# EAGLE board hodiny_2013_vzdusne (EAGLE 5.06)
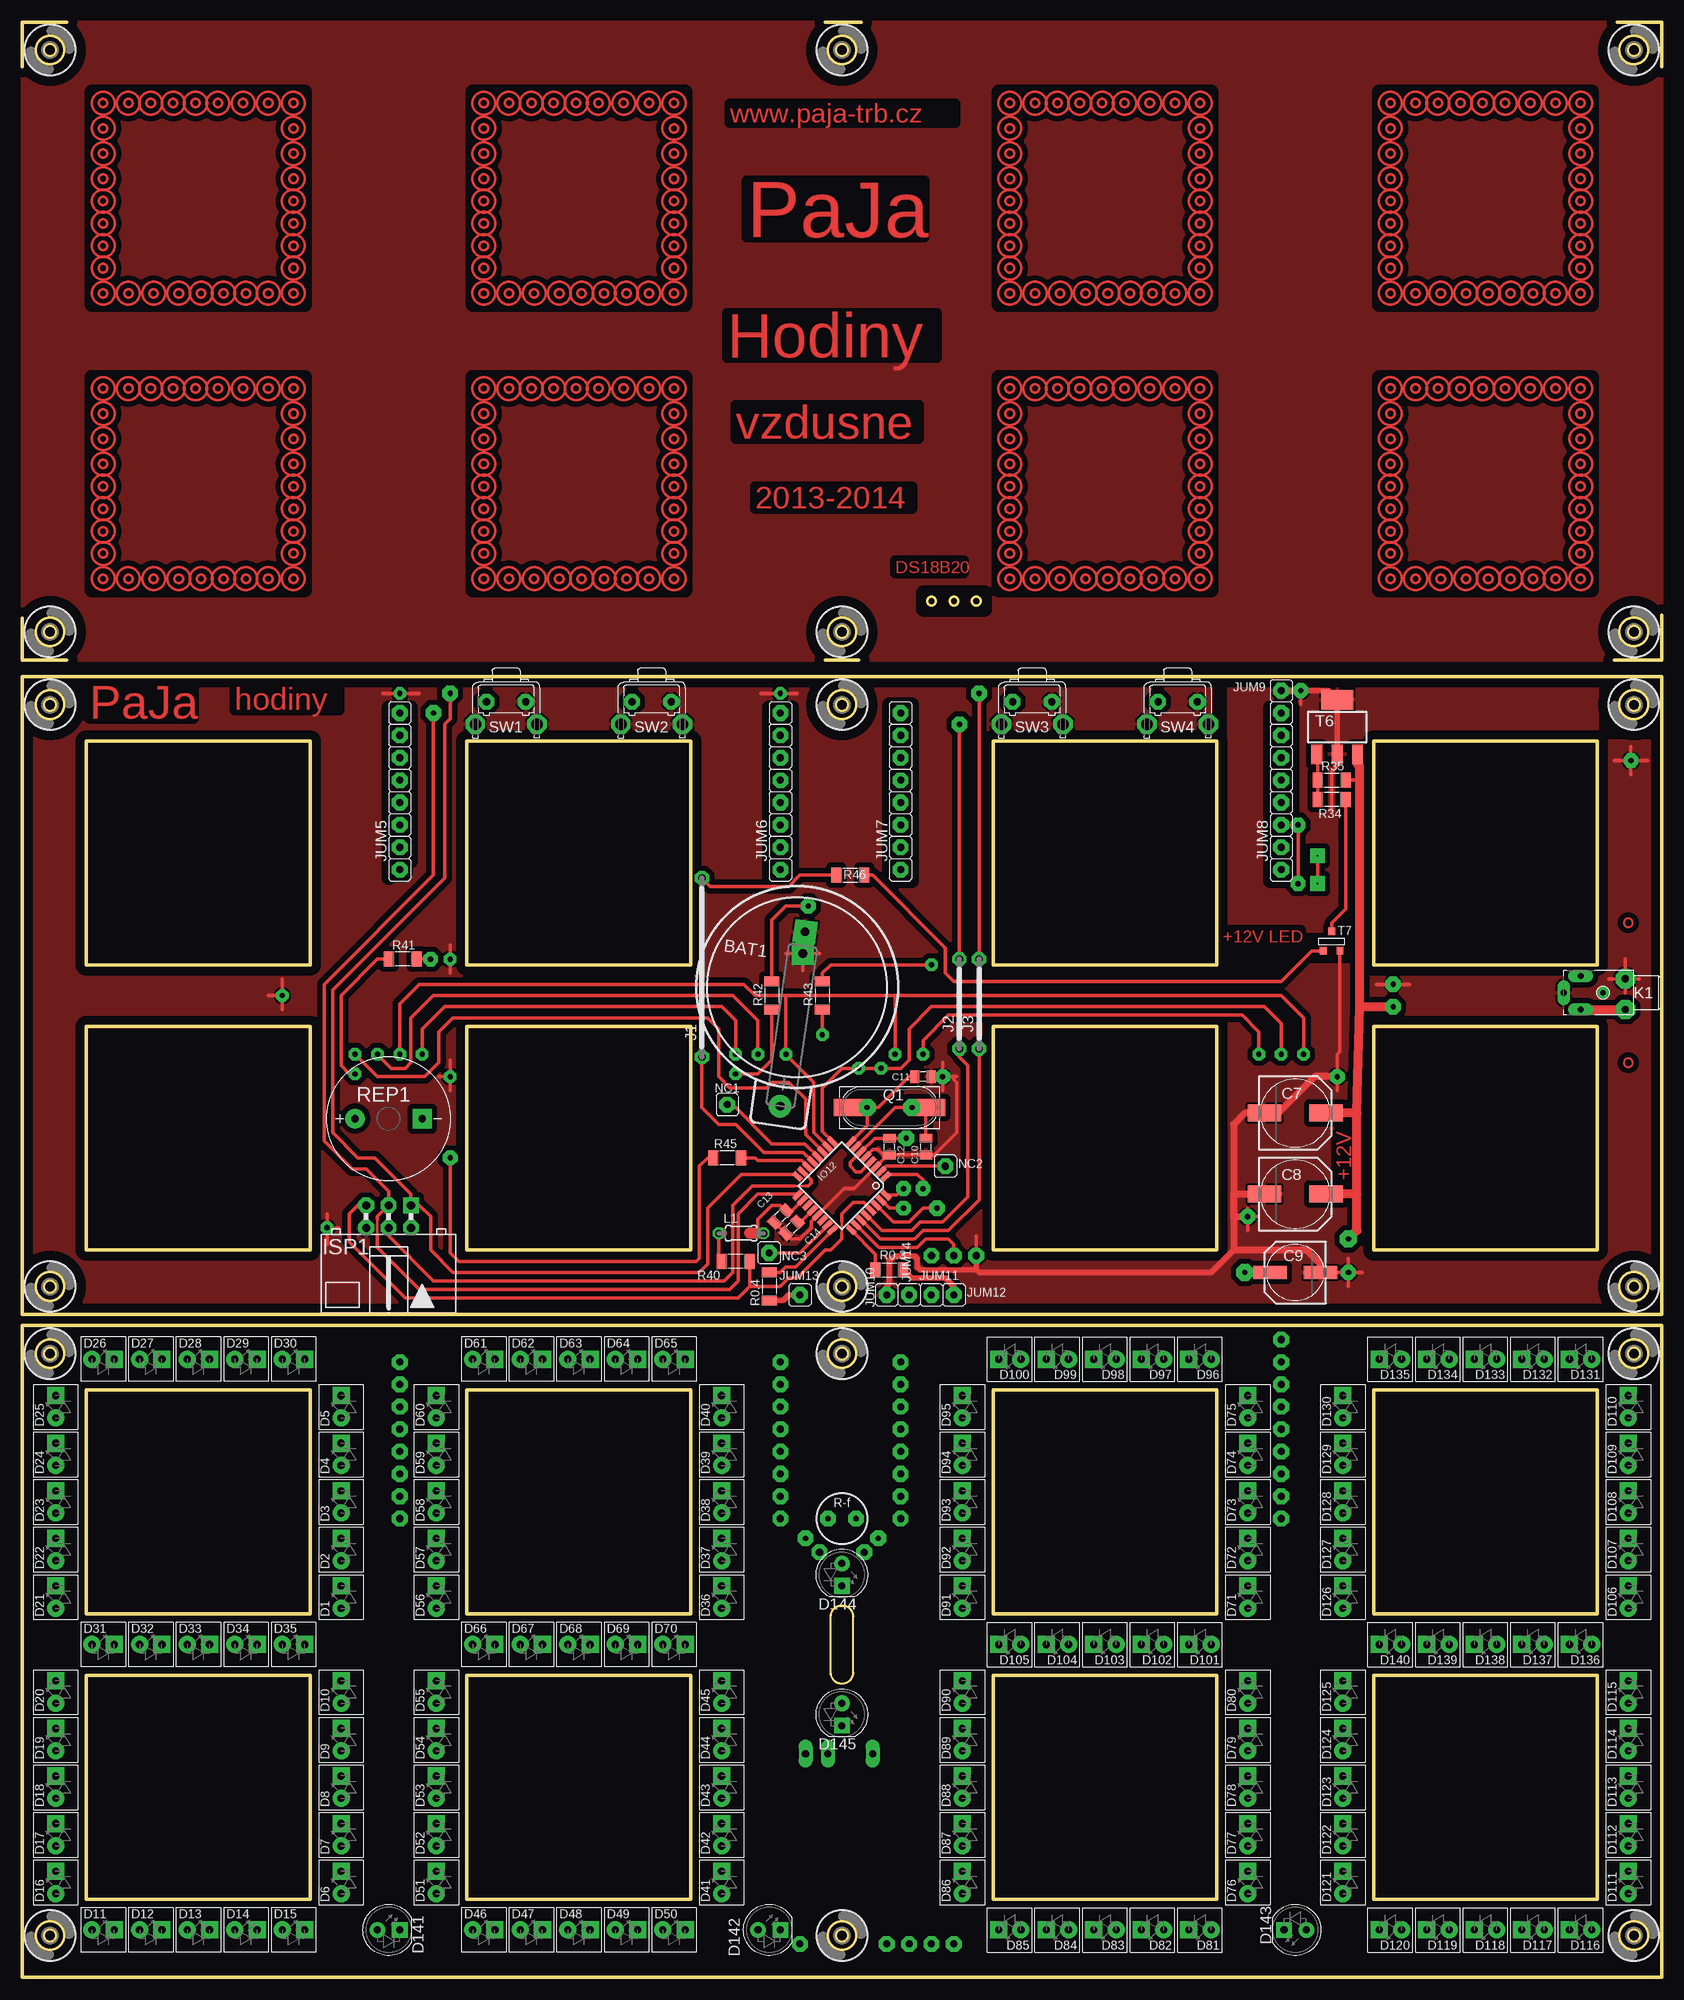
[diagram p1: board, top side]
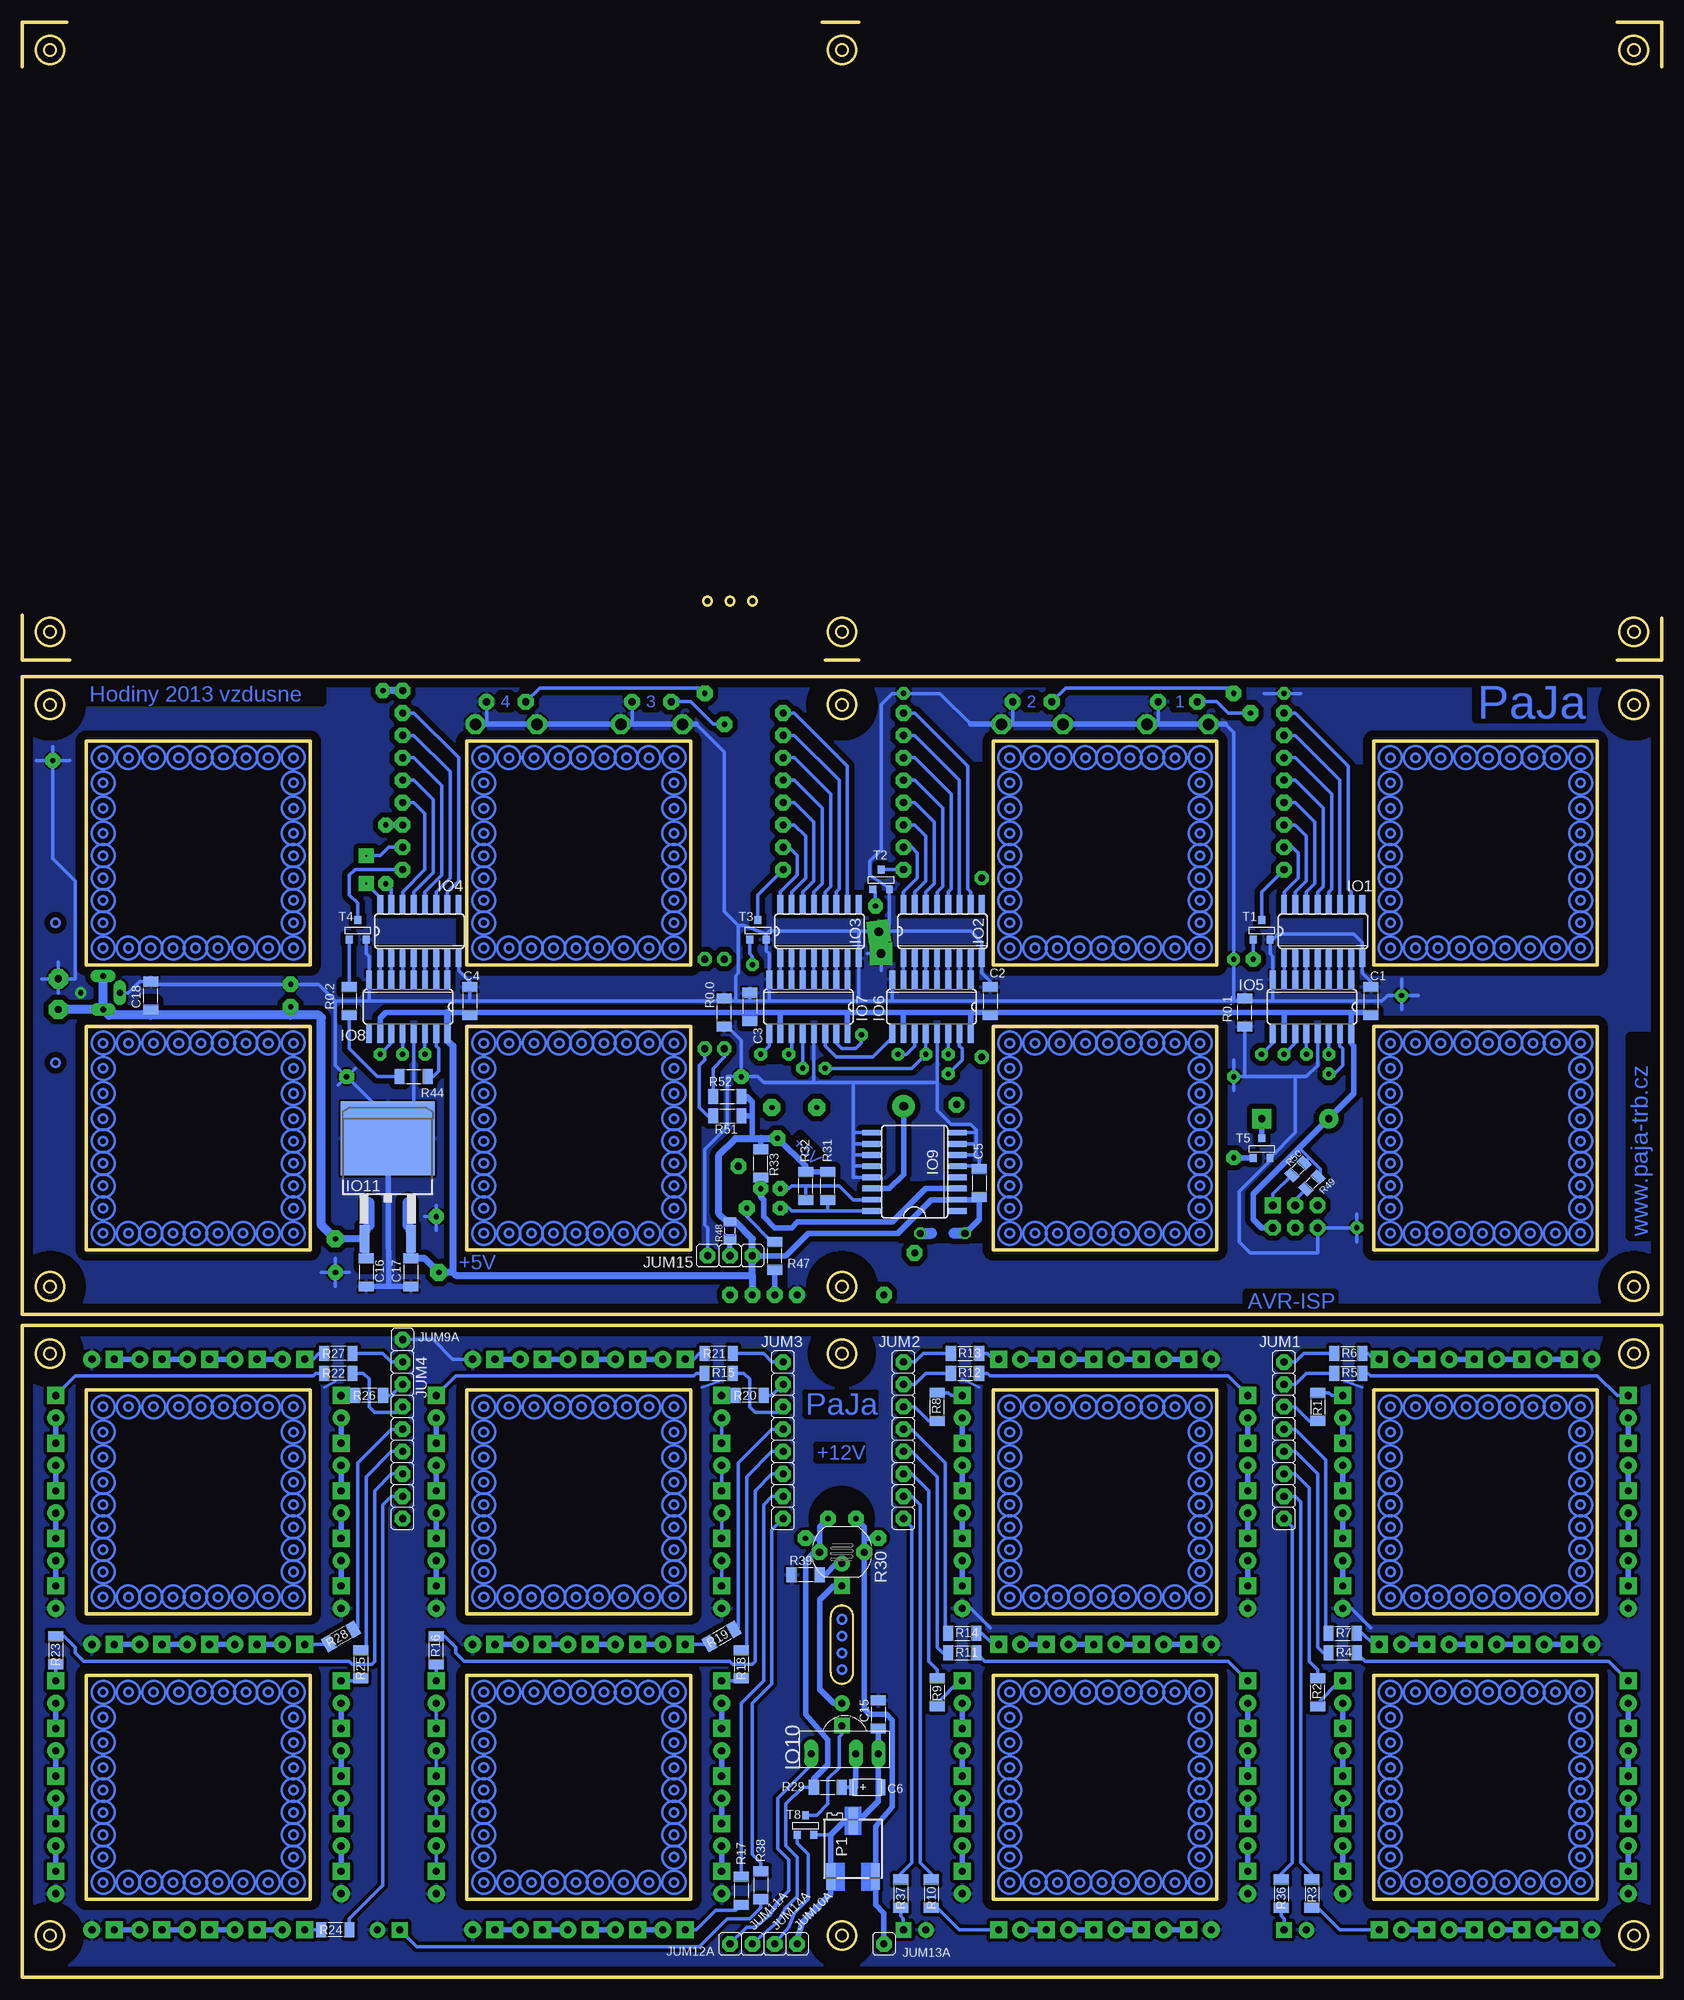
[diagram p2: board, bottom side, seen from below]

Size 186.06 x 221.93 mm. Coordinates in mm from the lower left corner, seen from the top.
Outline: 87 segments
Outline: circle at 103.19,156.21 radius 0.45
Outline: circle at 105.73,156.21 radius 0.45
Outline: circle at 108.27,156.21 radius 0.45
Copper layers (1*16): Top 0.035mm / dielectric 1.5mm / Bottom 0.035mm
Design rules "default": minimum track width 10mil, minimum drill 24mil, track to track 8mil, track to pad 8mil, pad to pad 8mil, via to via 8mil, smd to smd 8mil, copper to edge 40mil, drill to drill 8mil, minimum pad ring 10mil, minimum via ring 8mil, stop-mask expansion 4mil, vias tented up to drill 0mil, thermal gap 10mil
tRestrict: area 34.3,84.8 to 34.9,85.4; area 48.3,101.9 to 48.9,102.6; area 29.2,111.1 to 29.8,111.8; area 48.3,115.3 to 48.9,115.9; area 42.5,145.4 to 43.2,146.1; area 85.7,145.4 to 86.4,146.1; area 144.8,145.7 to 145.4,146.4; area 182.2,137.8 to 182.9,138.4; area 155.3,112.4 to 155.9,113; area 150.2,79.7 to 150.8,80.3; area 148.9,101.9 to 149.5,102.6; area 108,81.6 to 108.6,82.2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; 57 lines
bRestrict: area 78.7,91.4 to 81,96.2; area 88.6,91.4 to 90.8,96.2; area 34.3,84.8 to 34.9,85.4; area 48.3,101.9 to 48.9,102.6; area 29.2,111.1 to 29.8,111.8; area 48.3,115.3 to 48.9,115.9; area 42.5,145.4 to 43.2,146.1; area 85.7,145.4 to 86.4,146.1; area 144.8,145.7 to 145.4,146.4; area 182.2,137.8 to 182.9,138.4; area 155.3,112.4 to 155.9,113; area 150.2,79.7 to 150.8,80.3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; 18 lines

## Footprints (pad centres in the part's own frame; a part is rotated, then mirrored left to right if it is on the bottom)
SN2032 = drill 1 pad 2.54 round: + 13.652,0 | drill 1 pad 2.54 square: - -6.35,0
1206 = smd 1.143 x 1.702: 1 -1.587,0; 2 1.587,0
A = smd 0.914 x 1.778: + 1.587,0; - -1.587,0
C_EL-SMD_F = smd 3.81 x 1.93: + 3.493,0; - -3.493,0
C_EL-SMD_D = smd 3.81 x 1.473: + 2.857,0; - -2.857,0
0805 = smd 1.016 x 1.422: 1 -0.953,0; 2 0.953,0
LED_5X5 = drill 0.813 pad 1.93 round: A -1.27,0 | drill 0.813 pad 1.93 square: K 1.27,0
LED_5 = drill 0.813 pad 1.778 round: A -1.27,0 | drill 0.813 pad 1.778 square: K 1.27,0
SO16 = smd 0.66 x 2.032: 1 -4.445,-3.073; 2 -3.175,-3.073; 3 -1.905,-3.073; 4 -0.635,-3.073; 5 0.635,-3.073; 6 1.905,-3.073; 7 3.175,-3.073; 8 4.445,-3.073; 9 4.445,3.073; 10 3.175,3.073; 11 1.905,3.073; 12 0.635,3.073; 13 -0.635,3.073; 14 -1.905,3.073; 15 -3.175,3.073; 16 -4.445,3.073
SO16L = smd 0.66 x 2.032: 1 -4.445,-4.902; 2 -3.175,-4.902; 3 -1.905,-4.902; 4 -0.635,-4.902; 5 0.635,-4.902; 6 1.905,-4.902; 7 3.175,-4.902; 8 4.445,-4.902; 9 4.445,4.902; 10 3.175,4.902; 11 1.905,4.902; 12 0.635,4.902; 13 -0.635,4.902; 14 -1.905,4.902; 15 -3.175,4.902; 16 -4.445,4.902
SFH506 = drill 0.813 pad 1.6 long: 1 -3.81,0; 2 -1.27,0; 3 3.81,0
D2PAK = smd 1.1 x 3.1: 1 -2.641,-8.535; 3 2.641,-8.535 | smd 10.7 x 8.4: 4 0,2.817
TQFP32-08 = smd 1.27 x 0.559: 1 -4.293,2.8; 2 -4.293,2; 3 -4.293,1.2; 4 -4.293,0.4; 5 -4.293,-0.4; 6 -4.293,-1.2; 7 -4.293,-2; 8 -4.293,-2.8; 17 4.293,-2.8; 18 4.293,-2; 19 4.293,-1.2; 20 4.293,-0.4; 21 4.293,0.4; 22 4.293,1.2; 23 4.293,2; 24 4.293,2.8 | smd 0.559 x 1.27: 9 -2.8,-4.293; 10 -2,-4.293; 11 -1.2,-4.293; 12 -0.4,-4.293; 13 0.4,-4.293; 14 1.2,-4.293; 15 2,-4.293; 16 2.8,-4.293; 25 2.8,4.293; 26 2,4.293; 27 1.2,4.293; 28 0.4,4.293; 29 -0.4,4.293; 30 -1.2,4.293; 31 -2,4.293; 32 -2.8,4.293
MLW06A = drill 0.914 pad 1.778 square: 1 -2.54,-1.27 | drill 0.914 pad 1.778 octagon: 2 -2.54,1.27; 3 0,-1.27; 4 0,1.27; 5 2.54,-1.27; 6 2.54,1.27
20 = drill 0.813 pad 1.6 octagon: 1 -10.16,0; 2 10.16,0
10 = drill 0.813 pad 1.6 octagon: 1 -5.08,0; 2 5.08,0
S1G8_JUM = drill 0.813 pad 1.778 octagon: 1 -8.89,0; 2 -6.35,0; 3 -3.81,0; 4 -1.27,0; 5 1.27,0; 6 3.81,0; 7 6.35,0; 8 8.89,0
S1G1_JUM = drill 0.8 pad 1.778 octagon: 1 0,0
S1G3_JUM = drill 0.813 pad 1.778 octagon: 1 -2.54,0; 2 0,0; 3 2.54,0
CON_SCJ-0253A = drill 0.7 pad 1.422 long: 1 1.905,0; 2 0,-1.905; 3 0,1.905
0204/5 = drill 0.813 octagon: 1 -2.54,0; 2 2.54,0
RTRIMTS63Z = smd 1 x 3: 1 -2.55,-3.15; 2 0,3.15; 3 2.55,-3.15
HC-49US = smd 3.81 x 1.93: 1 -4.445,0; 2 4.445,0
R-FOTO = drill 0.813 pad 1.778 octagon: 1 -2.54,0; 2 2.54,0
KPE242 = drill 0.813 pad 2.184 round: + -3.81,0 | drill 0.813 pad 2.184 square: - 3.81,0
P-KSM632B = drill 0.813 pad 1.778 octagon: 1 -2.223,0; 2 2.223,0 | drill 1.3 pad 2.184 octagon: A -3.493,2.54; B 3.493,2.54
SOT-23 = smd 0.787 x 0.889: 1 -0.953,-0.953; 2 0.953,-0.953; 3 0,1.27
SOT223 = smd 1.219 x 2.235: 1 -2.311,-3.099; 2 0,-3.099; 3 2.311,-3.099 | smd 3.6 x 2.2: 4 0,3.099
HOLE_3,0 = hole 3.2: 0,0

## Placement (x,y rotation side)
BAT1  BAT-CR2032PCB2  [SN2032]  87.95,112.4 261.9 top
C1  100n  [1206]  33.02,110.81 270 bottom
C2  100n  [1206]  76.2,110.81 270 bottom
C3  100n  [1206]  103.5,110.17 270 bottom
C4  100n  [1206]  135.25,110.81 270 bottom
C5  100n  [1206]  77.47,90.17 270 bottom
C6  4M7/10V  [A]  90.17,21.59 180 bottom
C7  220M/16V  [C_EL-SMD_F]  144.46,98.11 0 top
C8  220M/16V  [C_EL-SMD_F]  144.46,88.9 0 top
C9  100M/16V  [C_EL-SMD_D]  144.46,80.01 180 top
C10  22  [0805]  102.55,94.3 90 top
C11  22  [0805]  102.23,102.23 180 top
C12  100n  [0805]  98.42,94.3 270 top
C13  100n  [0805]  86.04,86.36 225 top
C14  100n  [0805]  87.31,85.09 225 top
C15  100n  [1206]  88.9,29.84 270 bottom
C16  100n  [1206]  147,80.01 270 bottom
C17  100n  [1206]  141.92,80.01 270 bottom
C18  100n  [1206]  171.45,111.44 90 bottom
D1  zel  [LED_5X5]  36.2,43.18 90 top
D2  zel  [LED_5X5]  36.2,48.58 90 top
D3  zel  [LED_5X5]  36.2,53.98 90 top
D4  zel  [LED_5X5]  36.2,59.37 90 top
D5  zel  [LED_5X5]  36.2,64.77 90 top
D6  zel  [LED_5X5]  36.2,10.8 90 top
D7  zel  [LED_5X5]  36.2,16.19 90 top
D8  zel  [LED_5X5]  36.2,21.59 90 top
D9  zel  [LED_5X5]  36.2,26.99 90 top
D10  zel  [LED_5X5]  36.2,32.39 90 top
D11  zel  [LED_5X5]  9.21,5.4 0 top
D12  zel  [LED_5X5]  14.61,5.4 0 top
D13  zel  [LED_5X5]  20,5.4 0 top
D14  zel  [LED_5X5]  25.4,5.4 0 top
D15  zel  [LED_5X5]  30.8,5.4 0 top
D16  zel  [LED_5X5]  3.81,10.8 90 top
D17  zel  [LED_5X5]  3.81,16.19 90 top
D18  zel  [LED_5X5]  3.81,21.59 90 top
D19  zel  [LED_5X5]  3.81,26.99 90 top
D20  zel  [LED_5X5]  3.81,32.39 90 top
D21  zel  [LED_5X5]  3.81,43.18 90 top
D22  zel  [LED_5X5]  3.81,48.58 90 top
D23  zel  [LED_5X5]  3.81,53.98 90 top
D24  zel  [LED_5X5]  3.81,59.37 90 top
D25  zel  [LED_5X5]  3.81,64.77 90 top
D26  zel  [LED_5X5]  9.21,70.17 0 top
D27  zel  [LED_5X5]  14.61,70.17 0 top
D28  zel  [LED_5X5]  20,70.17 0 top
D29  zel  [LED_5X5]  25.4,70.17 0 top
D30  zel  [LED_5X5]  30.8,70.17 0 top
D31  zel  [LED_5X5]  9.21,37.78 0 top
D32  zel  [LED_5X5]  14.61,37.78 0 top
D33  zel  [LED_5X5]  20,37.78 0 top
D34  zel  [LED_5X5]  25.4,37.78 0 top
D35  zel  [LED_5X5]  30.8,37.78 0 top
D36  zel  [LED_5X5]  79.38,43.18 90 top
D37  zel  [LED_5X5]  79.38,48.58 90 top
D38  zel  [LED_5X5]  79.38,53.98 90 top
D39  zel  [LED_5X5]  79.38,59.37 90 top
D40  zel  [LED_5X5]  79.38,64.77 90 top
D41  zel  [LED_5X5]  79.38,10.8 90 top
D42  zel  [LED_5X5]  79.38,16.19 90 top
D43  zel  [LED_5X5]  79.38,21.59 90 top
D44  zel  [LED_5X5]  79.38,26.99 90 top
D45  zel  [LED_5X5]  79.38,32.39 90 top
D46  zel  [LED_5X5]  52.39,5.4 0 top
D47  zel  [LED_5X5]  57.78,5.4 0 top
D48  zel  [LED_5X5]  63.18,5.4 0 top
D49  zel  [LED_5X5]  68.58,5.4 0 top
D50  zel  [LED_5X5]  73.98,5.4 0 top
D51  zel  [LED_5X5]  46.99,10.8 90 top
D52  zel  [LED_5X5]  46.99,16.19 90 top
D53  zel  [LED_5X5]  46.99,21.59 90 top
D54  zel  [LED_5X5]  46.99,26.99 90 top
D55  zel  [LED_5X5]  46.99,32.39 90 top
D56  zel  [LED_5X5]  46.99,43.18 90 top
D57  zel  [LED_5X5]  46.99,48.58 90 top
D58  zel  [LED_5X5]  46.99,53.98 90 top
D59  zel  [LED_5X5]  46.99,59.37 90 top
D60  zel  [LED_5X5]  46.99,64.77 90 top
D61  zel  [LED_5X5]  52.39,70.17 0 top
D62  zel  [LED_5X5]  57.78,70.17 0 top
D63  zel  [LED_5X5]  63.18,70.17 0 top
D64  zel  [LED_5X5]  68.58,70.17 0 top
D65  zel  [LED_5X5]  73.98,70.17 0 top
D66  zel  [LED_5X5]  52.39,37.78 0 top
D67  zel  [LED_5X5]  57.78,37.78 0 top
D68  zel  [LED_5X5]  63.18,37.78 0 top
D69  zel  [LED_5X5]  68.58,37.78 0 top
D70  zel  [LED_5X5]  73.98,37.78 0 top
D71  zel  [LED_5X5]  139.06,43.18 90 top
D72  zel  [LED_5X5]  139.06,48.58 90 top
D73  zel  [LED_5X5]  139.06,53.98 90 top
D74  zel  [LED_5X5]  139.06,59.37 90 top
D75  zel  [LED_5X5]  139.06,64.77 90 top
D76  zel  [LED_5X5]  139.06,10.8 90 top
D77  zel  [LED_5X5]  139.06,16.19 90 top
D78  zel  [LED_5X5]  139.06,21.59 90 top
D79  zel  [LED_5X5]  139.06,26.99 90 top
D80  zel  [LED_5X5]  139.06,32.39 90 top
D81  zel  [LED_5X5]  133.67,5.4 180 top
D82  zel  [LED_5X5]  128.27,5.4 180 top
D83  zel  [LED_5X5]  122.87,5.4 180 top
D84  zel  [LED_5X5]  117.47,5.4 180 top
D85  zel  [LED_5X5]  112.08,5.4 180 top
D86  zel  [LED_5X5]  106.68,10.8 90 top
D87  zel  [LED_5X5]  106.68,16.19 90 top
D88  zel  [LED_5X5]  106.68,21.59 90 top
D89  zel  [LED_5X5]  106.68,26.99 90 top
D90  zel  [LED_5X5]  106.68,32.39 90 top
D91  zel  [LED_5X5]  106.68,43.18 90 top
D92  zel  [LED_5X5]  106.68,48.58 90 top
D93  zel  [LED_5X5]  106.68,53.98 90 top
D94  zel  [LED_5X5]  106.68,59.37 90 top
D95  zel  [LED_5X5]  106.68,64.77 90 top
D96  zel  [LED_5X5]  133.67,70.17 180 top
D97  zel  [LED_5X5]  128.27,70.17 180 top
D98  zel  [LED_5X5]  122.87,70.17 180 top
D99  zel  [LED_5X5]  117.47,70.17 180 top
D100  zel  [LED_5X5]  112.08,70.17 180 top
D101  zel  [LED_5X5]  133.67,37.78 180 top
D102  zel  [LED_5X5]  128.27,37.78 180 top
D103  zel  [LED_5X5]  122.87,37.78 180 top
D104  zel  [LED_5X5]  117.47,37.78 180 top
D105  zel  [LED_5X5]  112.08,37.78 180 top
D106  zel  [LED_5X5]  182.25,43.18 90 top
D107  zel  [LED_5X5]  182.25,48.58 90 top
D108  zel  [LED_5X5]  182.25,53.98 90 top
D109  zel  [LED_5X5]  182.25,59.37 90 top
D110  zel  [LED_5X5]  182.25,64.77 90 top
D111  zel  [LED_5X5]  182.25,10.8 90 top
D112  zel  [LED_5X5]  182.25,16.19 90 top
D113  zel  [LED_5X5]  182.25,21.59 90 top
D114  zel  [LED_5X5]  182.25,26.99 90 top
D115  zel  [LED_5X5]  182.25,32.39 90 top
D116  zel  [LED_5X5]  176.85,5.4 180 top
D117  zel  [LED_5X5]  171.45,5.4 180 top
D118  zel  [LED_5X5]  166.05,5.4 180 top
D119  zel  [LED_5X5]  160.66,5.4 180 top
D120  zel  [LED_5X5]  155.26,5.4 180 top
D121  zel  [LED_5X5]  149.86,10.8 90 top
D122  zel  [LED_5X5]  149.86,16.19 90 top
D123  zel  [LED_5X5]  149.86,21.59 90 top
D124  zel  [LED_5X5]  149.86,26.99 90 top
D125  zel  [LED_5X5]  149.86,32.39 90 top
D126  zel  [LED_5X5]  149.86,43.18 90 top
D127  zel  [LED_5X5]  149.86,48.58 90 top
D128  zel  [LED_5X5]  149.86,53.98 90 top
D129  zel  [LED_5X5]  149.86,59.37 90 top
D130  zel  [LED_5X5]  149.86,64.77 90 top
D131  zel  [LED_5X5]  176.85,70.17 180 top
D132  zel  [LED_5X5]  171.45,70.17 180 top
D133  zel  [LED_5X5]  166.05,70.17 180 top
D134  zel  [LED_5X5]  160.66,70.17 180 top
D135  zel  [LED_5X5]  155.26,70.17 180 top
D136  zel  [LED_5X5]  176.85,37.78 180 top
D137  zel  [LED_5X5]  171.45,37.78 180 top
D138  zel  [LED_5X5]  166.05,37.78 180 top
D139  zel  [LED_5X5]  160.66,37.78 180 top
D140  zel  [LED_5X5]  155.26,37.78 180 top
D141  ZEL  [LED_5]  41.59,5.4 0 top
D142  ZEL  [LED_5]  84.77,5.4 0 top
D143  ZEL  [LED_5]  144.46,5.4 180 top
D144  ZEL  [LED_5]  93.03,45.72 270 top
D145  ZEL  [LED_5]  93.03,29.84 270 top
IO1  ULN2003  [SO16]  38.42,118.75 0 bottom
IO2  ULN2003  [SO16]  81.6,118.75 0 bottom
IO3  ULN2003  [SO16]  95.57,118.75 0 bottom
IO4  ULN2003  [SO16]  140.97,118.75 0 bottom
IO5  74HCT595D  [SO16]  39.69,110.17 180 bottom
IO6  74HCT595D  [SO16]  82.87,110.17 180 bottom
IO7  74HCT595D  [SO16]  96.84,110.17 180 bottom
IO8  74HCT595D  [SO16]  142.24,110.17 180 bottom
IO9  DS3231  [SO16L]  84.77,91.44 90 bottom
IO10  TSOP31236  [SFH506]  92.71,25.4 180 bottom
IO11  7805ABD2T  [D2PAK]  144.56,92.39 0 bottom
IO12  ATmega168-20AU  [TQFP32-08]  93.03,89.85 225 top
ISP1  AVR_ISP_90°  [MLW06A]  41.59,86.36 180 top
J1  J20MM  [20]  77.15,114.62 90 top
J2  J10MM  [10]  106.36,110.49 90 top
J3  J10MM  [10]  108.59,110.49 90 top
JUM1  S1G8  [S1G8_JUM]  42.86,60.96 270 bottom
JUM2  S1G8  [S1G8_JUM]  86.04,60.96 270 bottom
JUM3  S1G8  [S1G8_JUM]  99.7,60.96 270 bottom
JUM4  S1G8  [S1G8_JUM]  142.88,60.96 270 bottom
JUM5  S1G8_JUMP  [S1G8_JUM]  42.86,134.62 90 top
JUM6  S1G8_JUMP  [S1G8_JUM]  86.04,134.62 90 top
JUM7  S1G8_JUMP  [S1G8_JUM]  99.7,134.62 90 top
JUM8  S1G8_JUMP  [S1G8_JUM]  142.88,134.62 90 top
JUM9  .  [S1G1_JUM]  142.88,146.05 90 top
JUM9A  .  [S1G1_JUM]  142.88,72.39 0 bottom
JUM10  .  [S1G1_JUM]  98.11,77.47 90 top
JUM10A  .  [S1G1_JUM]  98.11,3.81 0 bottom
JUM11  .  [S1G1_JUM]  103.19,77.47 90 top
JUM11A  .  [S1G1_JUM]  103.19,3.81 0 bottom
JUM12  .  [S1G1_JUM]  105.73,77.47 90 top
JUM12A  .  [S1G1_JUM]  105.73,3.81 0 bottom
JUM13  .  [S1G1_JUM]  88.27,77.47 90 top
JUM13A  .  [S1G1_JUM]  88.27,3.81 0 bottom
JUM14  .  [S1G1_JUM]  100.65,77.47 90 top
JUM14A  .  [S1G1_JUM]  100.65,3.81 0 bottom
JUM15  DS18B20  [S1G3_JUM]  105.73,81.92 0 bottom
K1  SCJ-0253A  [CON_SCJ-0253A]  176.85,111.76 180 top
L1  10uH  [0204/5]  81.6,84.45 0 top
NC1  S1G1_JUMP  [S1G1_JUM]  80.01,99.06 0 top
NC2  S1G1_JUMP  [S1G1_JUM]  104.78,92.08 0 top
NC3  S1G1_JUMP  [S1G1_JUM]  84.77,82.23 0 top
P1  5k  [RTRIMTS63Z]  91.76,14.61 0 bottom
Q1  8MHz  [HC-49US]  98.42,98.74 0 top
R0.0  0R  [1206]  106.36,109.54 90 bottom
R0.1  0R  [1206]  47.31,109.54 90 bottom
R0.2  0R  [1206]  148.91,110.81 270 bottom
R0.3  0R  [1206]  98.42,80.33 0 top
R0.4  0R  [1206]  84.77,78.42 270 top
R1  100  [1206]  39.05,64.77 270 bottom
R2  100  [1206]  39.05,32.39 90 bottom
R3  100  [1206]  39.69,9.53 270 bottom
R4  100  [1206]  36.2,36.83 0 bottom
R5  100  [1206]  35.56,68.58 0 bottom
R6  100  [1206]  35.56,70.8 0 bottom
R7  100  [1206]  36.2,39.05 0 bottom
R8  100  [1206]  82.23,64.77 90 bottom
R9  100  [1206]  82.23,32.39 270 bottom
R10  100  [1206]  82.87,9.53 270 bottom
R11  100  [1206]  79.38,36.83 0 bottom
R12  100  [1206]  79.06,68.58 0 bottom
R13  100  [1206]  79.06,70.8 0 bottom
R14  100  [1206]  79.38,39.05 0 bottom
R15  100  [1206]  107,68.58 0 bottom
R16  100  [1206]  139.06,37.15 90 bottom
R17  100  [1206]  104.46,9.84 270 bottom
R18  100  [1206]  104.46,35.56 270 bottom
R19  100  [1206]  106.68,38.73 210 bottom
R20  100  [1206]  103.5,66.04 180 bottom
R21  100  [1206]  107,70.8 180 bottom
R22  100  [1206]  150.18,68.58 180 bottom
R23  100  [1206]  182.25,37.15 270 bottom
R24  100  [1206]  150.5,5.4 180 bottom
R25  100  [1206]  147.64,35.56 270 bottom
R26  100  [1206]  146.69,66.04 180 bottom
R27  100  [1206]  150.18,70.8 180 bottom
R28  100  [1206]  149.86,38.73 210 bottom
R29  220  [1206]  94.62,21.59 0 bottom
R30  VT43N1 (A906013)  [R-FOTO]  93.03,48.26 180 bottom
R31  10k  [1206]  94.62,89.85 90 bottom
R32  10k  [1206]  97.16,89.85 90 bottom
R33  10k  [1206]  102.23,92.39 90 bottom
R34  1k  [1206]  148.59,133.67 180 top
R35  22k  [1206]  148.59,135.89 0 top
R36  820  [1206]  43.18,9.53 270 bottom
R37  820  [1206]  86.36,9.53 270 bottom
R38  820  [1206]  102.23,10.48 270 bottom
R39  680  [1206]  97.16,45.72 180 bottom
R40  4k7  [1206]  80.96,81.28 180 top
R41  4k7  [1206]  43.18,115.57 180 top
R42  4k7  [1206]  85.09,111.44 270 top
R43  4k7  [1206]  90.81,111.44 270 top
R44  4k7  [1206]  141.61,102.23 0 bottom
R45  4k7  [1206]  80.01,93.03 180 top
R46  4k7  [1206]  93.98,125.09 0 top
R47  4k7  [1206]  100.65,81.92 90 bottom
R48  4k7  [0805]  105.73,84.77 90 bottom
R49  ne-10k  [0805]  39.69,90.17 225 bottom
R50  ne-10k  [0805]  41.27,91.76 225 bottom
R51  ne-10k  [1206]  106.05,97.79 0 bottom
R52  ne-10k  [1206]  106.05,100.01 0 bottom
REP1  KPE242  [KPE242]  41.59,97.47 0 top
SW1  TACTA-68N-F  [P-KSM632B]  54.93,144.78 180 top
SW2  TACTA-68N-F  [P-KSM632B]  71.44,144.78 180 top
SW3  TACTA-68N-F  [P-KSM632B]  114.62,144.78 180 top
SW4  TACTA-68N-F  [P-KSM632B]  131.13,144.78 180 top
T1  BC846  [SOT-23]  45.4,118.75 0 bottom
T2  BC846  [SOT-23]  88.58,124.46 0 bottom
T3  BC846  [SOT-23]  102.55,118.75 0 bottom
T4  BC846  [SOT-23]  147.95,118.75 0 bottom
T5  BC817  [SOT-23]  45.4,93.98 0 bottom
T6  BCP53-16  [SOT223]  149.22,141.92 0 top
T7  BC817  [SOT-23]  148.59,117.47 0 top
T8  BC817  [SOT-23]  97.16,17.15 0 bottom
U$1  [HOLE_3,0]  3.18,4.76 0 top
U$2  [HOLE_3,0]  182.88,4.76 0 top
U$3  [HOLE_3,0]  182.88,70.8 0 top
U$4  [HOLE_3,0]  3.18,70.8 0 top
U$5  [HOLE_3,0]  93.03,4.76 0 top
U$6  [HOLE_3,0]  93.03,70.8 0 top
U$7  [HOLE_3,0]  93.03,78.42 0 top
U$8  [HOLE_3,0]  182.88,78.42 0 top
U$9  [HOLE_3,0]  182.88,144.46 0 top
U$10  [HOLE_3,0]  93.03,144.46 0 top
U$11  [HOLE_3,0]  3.18,144.46 0 top
U$12  [HOLE_3,0]  3.18,78.42 0 top
U$13  [HOLE_3,0]  3.18,152.72 0 top
U$14  [HOLE_3,0]  3.18,218.76 0 top
U$15  [HOLE_3,0]  182.88,218.76 0 top
U$16  [HOLE_3,0]  182.88,152.72 0 top
U$17  [HOLE_3,0]  93.03,152.72 0 top
U$18  [HOLE_3,0]  93.03,218.76 0 top

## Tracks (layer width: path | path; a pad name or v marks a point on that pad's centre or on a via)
0V
  Bottom 0.406: 88.9,24.13 88.9,23.81 | 88.9,21.59 C6.- | 94.3,16.19 T8.2
  Bottom 0.61: JUM10A.1 98.11,4.45 97.47,6.35 94.31,9.51 P1.1 94.31,13.33 94.3,16.19 92.71,17.78 92.08,17.78 P1.2 91.76,17.78 91.12,17.78 88.9,20 88.9,21.59 88.9,24.13 IO10.1 C15.2
1HZ  (via drill 0.6 pad 1.68)
  Top 0.406: IO12.1 98.26,91.12 101.6,91.12 102.23,90.49 v102.23,89.53
  Bottom 0.61: IO9.3 83.5,89.53 87.31,85.72 98.11,85.72 98.74,85.09 100.65,85.09 101.92,86.36 101.92,88.27 102.23,88.58 v102.23,89.53 R33.1
+5V  (via drill 0.6 pad 1.78, 0.6 pad 1.93)
  Top 0.406: IO12.4 95.18,91.44 R31.2 93.98,92.08 93.98,92.5 IO12.6 96.73,95.25 C12.1 v100.33,95.25 | R40.2 79.06,81.6 L1.1
  Top 0.813: v138.75,80.01 C9.+
  Top 1.27: L1.1 79.38,84.45
  Bottom 0.406: 33.02,109.54 C1.2 | 99.7,109.54 100.01,109.54 | 76.2,109.54 C2.2 | 135.25,109.54 C4.2 | 77.79,88.27 C5.2 | R49.1 38.73,91.12 38.73,91.76 40.01,93.03 | 40.01,93.03 40.96,93.98 40.96,94.3 | 40.01,93.03 R50.1
  Bottom 0.61: 35.24,109.54 42.86,109.54 | 42.86,109.54 76.2,109.54 78.42,109.54 | 78.42,109.54 86.04,109.54 | 86.04,109.54 92.39,109.54 | 92.39,109.54 99.7,109.54 103.5,109.54 | 35.24,109.54 IO5.16 35.24,106.04 34.93,105.73 34.93,100.33 REP1.+ 40.96,94.3 46.36,88.9 46.36,86.04 45.4,85.09 ISP1.2 | 35.24,109.54 33.02,109.54 | 42.86,109.54 IO5.10 | 78.42,109.54 IO6.16 | 86.04,109.54 IO6.10 | 92.39,109.54 IO7.16 | 100.01,109.54 IO7.10 | 103.5,109.54 C3.2 | 103.5,109.54 135.25,109.54 137.8,109.54 144.78,109.54 145.42,108.9 IO8.10 | 77.79,88.27 IO9.2 82.87,88.27 86.68,84.45 96.84,84.45 99.38,81.92 JUM15.3 | L1.1 77.47,86.04 C5.2 | R31.2 R32.2 97.16,92.08 v100.33,95.25 | 102.23,95.25 R33.2 | R52.2 103.82,100.01 103.19,99.38 103.19,97.79 | 103.19,95.25 103.19,97.79 | 103.19,97.79 R51.2
  Bottom 0.813: 137.8,109.54 IO8.16 137.8,106.36 137.16,105.73 137.16,80.01 | 137.16,80.01 136.84,79.69 103.19,79.69 | v100.33,95.25 102.23,95.25 103.19,95.25 105.09,95.25 107,93.35 107,86.68 106.05,85.72 R48.2 105.09,85.72 103.19,83.82 JUM15.3 103.19,79.69 | 103.19,79.69 JUM11.1 | 137.16,80.01 v138.75,80.01 140.34,81.6 C17.1 IO11.3 142.24,85.41
  Bottom 1.27: 142.24,85.41 142.24,87.95 | L1.1 80.33,84.45
  other vias: 103.19,81.92
+5VDC  (via drill 0.6 pad 1.78)
  Bottom 0.406: JUM11A.1 100.33,6.35 99.38,7.94 98.11,9.21 98.11,13.65 99.38,14.92 99.38,19.69 97.47,21.59 R29.1
  Bottom 0.61: R29.1 96.2,22.54 94.62,24.13 94.62,26.99 97.16,29.84 97.16,47.31 96.2,48.26 R30.2 95.57,49.85 | 95.57,49.85 v97.16,49.85 | v94.62,52.07 95.57,51.12 95.57,49.85
+12V
  Bottom 0.305: 151.76,66.99 150.5,67.63 | 107,67.63 108.9,66.99 | 77.47,66.99 79.38,67.94 | 35.88,67.63 33.97,66.99
  Bottom 0.406: D96.A 137.16,70.17 139.38,72.39 JUM9A.1 | 33.02,39.69 35.24,41.91 D1.A | D36.A 78.42,41.91 76.2,39.69
  pour Bottom (isolate 0.406): 0,0 186.06,0 186.06,73.98 0,73.98
CLK  (via drill 0.6 pad 1.42)
  Top 0.406: 99.06,111.44 v99.06,104.77 | 99.06,111.44 142.88,111.44 145.42,108.9 v145.42,104.77 | 86.68,111.44 83.19,111.44 81.91,112.71 45.09,112.71 42.86,110.49 v42.86,104.77 | 86.68,111.44 99.06,111.44 | 86.68,111.44 v86.68,104.77 89.85,101.6 89.85,95.88 91.41,94.33 IO12.10
  Bottom 0.406: IO5.11 41.59,106.04 v42.86,104.77 | IO7.11 98.74,105.09 v99.06,104.77 | IO8.11 144.14,106.04 v145.42,104.77 | IO6.11 84.77,105.73 85.72,104.77 v86.68,104.77
DATA  (via drill 0.6 pad 1.42)
  Top 0.406: v37.78,104.77 40.32,102.24 45.72,102.24 47.31,103.82 47.31,107.32 48.9,108.9 77.79,108.9 79.06,107.63 79.06,102.24 80.33,100.97 84.45,100.97 85.09,101.6 87,101.6 88.9,99.7 88.9,95.68 IO12.11
  Bottom 0.406: v37.78,104.77 IO5.14
DATA1  (via drill 0.6 pad 1.42)
  Top 0.406: v80.96,104.77 80.96,108.58 79.38,110.17 47.94,110.17 45.4,107.63 v45.4,104.77
  Bottom 0.406: v80.96,104.77 IO6.14 | IO5.9 44.13,106.04 v45.4,104.77
DATA2
  Bottom 0.406: IO7.14 94.93,105.73 93.66,104.46 89.53,104.46 87.31,106.68 IO6.9
DATA3  (via drill 0.6 pad 1.42)
  Top 0.406: v102.23,104.77 102.23,106.36 105.09,109.22 138.43,109.22 140.34,107.32 v140.34,104.77
  Bottom 0.406: v140.34,104.77 IO8.14 | IO7.9 101.28,105.73 v102.23,104.77
DS18B20
  Top 0.406: IO12.26 97.18,82.87 101.6,82.87 102.55,83.82 105.09,83.82 105.73,83.19 JUM15.2
  Bottom 0.61: JUM15.2 R48.1
GND  (via drill 0.6 pad 1.27, 0.6 pad 1.42, 0.6 pad 1.68, 0.6 pad 1.78, 0.8 pad 2.18, 1 pad 2.54)
  Top 0.406: v104.46,102.24 C11.1 v104.46,102.24 | IO12.5 95.78,93.24 96.52,93.98 97.16,93.98 97.79,93.35 | 97.79,93.35 97.79,92.92 IO12.3 94.41,89.53 93.28,89.53 IO12.21 89.53,85.79 89.53,85.09 88.27,83.82 87.23,83.82 C14.2 C13.2 | 97.79,93.35 C12.2 C10.1 103.5,93.35 106.05,95.88 106.05,101.6 105.41,102.24 v104.46,102.24 | v34.61,85.09 34.61,86.68 | v34.61,85.09 34.61,83.19 | v34.61,85.09 35.88,85.09 | v29.53,111.44 29.53,113.35 | v29.53,111.44 29.53,109.86 | 27.94,111.44 v29.53,111.44 | 40.96,145.73 v42.86,145.73 45.09,145.73 | 87.95,145.73 v86.04,145.73 83.82,145.73 | v182.56,138.11 182.56,139.7 | v182.56,138.11 182.56,136.53 | v182.56,138.11 180.66,138.11 | v182.56,138.11 184.47,138.11 | v181.93,113.35 183.52,113.35 | v181.93,113.35 180.02,113.35 | v181.93,113.35 181.93,115.57 | 153.67,112.71 v155.57,112.71 157.48,112.71 | v150.5,80.01 152.08,80.01 | v150.5,80.01 150.5,81.6 | v150.5,80.01 150.5,78.42 | C9.- v150.5,80.01 | JUM15.1 108.27,84.14 | v48.58,102.24 48.58,104.14 | v48.58,102.24 48.58,100.65 | v48.58,102.24 47.31,102.24 | 48.58,117.16 v48.58,115.57 48.58,113.98 | v104.46,102.24 106.05,102.24 | v104.46,102.24 104.46,103.82 | v104.46,102.24 104.46,100.65 | v181.93,113.35 181.93,111.76 | v139.06,86.36 140.34,86.36 | v139.06,86.36 139.06,87.31 | v139.06,86.36 139.06,84.77 | 149.22,100.65 v149.22,102.24 149.22,104.77 149.54,105.09 T7.2 | v88.58,116.21 86.68,116.21 | v88.58,116.21 90.49,116.21 | v88.58,116.21 88.58,114.3
  Top 0.61: 141.61,98.11 C7.- | JUM10.1 98.11,78.42 98.42,78.74 98.42,81.28 99.06,81.92 101.28,81.92 101.6,81.6 101.6,80.64 101.92,80.33 108.27,80.33 | 137.48,82.55 134.94,80.01 108.59,80.01 108.27,80.33 | 108.27,80.33 JUM15.1
  Top 0.813: C7.- 138.75,98.11 137.48,96.84 137.48,86.36 | 137.48,86.36 137.48,82.55 145.73,82.55 147.32,80.96 C9.- | 137.48,86.36 137.48,88.9 C8.- | 137.48,86.36 v139.06,86.36 | v149.22,102.24 146.69,102.24 142.56,98.11 141.61,98.11
  Bottom 0.406: 44.13,113.35 IO5.8 | 44.13,113.35 44.13,115.89 44.45,116.21 T1.2 44.13,117.79 43.5,118.43 34.93,118.43 33.97,117.47 IO1.8 33.97,113.98 33.02,113.03 C1.1 | 87.63,118.75 78.42,118.75 77.15,117.47 IO2.8 77.15,113.98 76.2,113.03 C2.1 | 91.12,118.75 IO3.8 | IO4.8 136.53,114.3 135.25,113.03 C4.1 135.25,110.81 | T4.2 147,116.21 146.69,115.89 IO8.8 146.69,110.81 | 44.13,110.81 31.75,110.81 31.12,111.44 v29.53,111.44 | 44.13,110.81 47.31,110.81 | 47.31,110.81 48.58,110.81 | 48.58,110.81 87.31,110.81 | 87.31,110.81 91.12,110.81 | 101.28,110.81 103.5,110.81 | 103.5,110.81 105.09,110.81 | 105.09,110.81 106.36,110.81 | 106.36,110.81 135.25,110.81 | 135.25,110.81 146.69,110.81 | 146.69,110.81 150.5,110.81 | 44.13,110.81 44.13,113.35 | 87.31,110.81 IO6.8 | 101.28,110.81 IO7.8 101.28,116.21 101.6,116.52 T3.2 101.6,118.43 | 91.12,110.81 101.28,110.81 | 91.12,110.81 91.12,115.57 | 82.23,101.6 IO6.13 | 96.2,101.6 91.76,101.6 | 103.5,110.81 C3.1 | 87.63,118.75 T2.2 87.95,123.83 89.85,125.09 89.85,126.68 88.58,127.95 88.58,144.46 87.31,145.73 v86.04,145.73 81.91,145.73 78.42,142.24 | IO9.5 77.47,92.08 C5.1 77.47,93.03 77.79,93.35 | 77.79,95.88 IO9.8 | 77.79,94.61 77.79,93.35 | 77.79,95.88 77.79,94.61 | 77.79,93.35 IO9.6 | 77.79,94.61 IO9.7 | 91.76,95.88 IO9.9 | 91.76,92.08 91.76,90.8 IO9.13 | 91.76,93.35 91.76,92.08 | 91.76,94.61 91.76,93.35 | 91.76,95.88 91.76,94.61 | 91.76,92.08 IO9.12 | 91.76,93.35 IO9.11 | 91.76,94.61 IO9.10 | 77.79,95.88 77.79,96.2 78.42,96.84 80.65,96.84 82.23,98.42 82.23,101.6 | IO11.4 144.46,94.93 | 106.36,110.81 R0.0.2 | 96.2,101.6 IO7.13 | 41.59,102.24 47.31,102.24 | 47.31,110.81 R0.1.2 | 47.31,102.24 R0.1.1
  Bottom 0.406: 150.5,110.81 150.5,103.51 v149.22,102.24 | IO8.13 141.61,97.75 IO11.4 | 144.46,97.47 144.46,96.2 | v149.22,102.24 144.46,97.47 | 144.46,97.47 IO11.4 | 41.59,102.24 41.59,95.88 T5.2 44.45,92.71 47.94,89.22 47.94,83.5 46.67,82.23 39.05,82.23 ISP1.6 v34.61,85.09 | 47.31,102.24 v48.58,102.24 | IO5.13 39.05,103.51 40.32,102.24 41.59,102.24 | 57.15,142.24 SW1.1 | 73.66,142.24 SW2.1 | 116.84,142.24 SW3.1 | 133.35,142.24 SW4.1 | 105.09,110.81 105.09,113.66 104.78,113.98 104.78,119.38 | R0.0.1 106.05,107.95 104.46,106.36 v104.46,102.24 | 109.54,142.24 106.36,139.07 106.36,120.97 104.78,119.38 | 104.78,119.38 104.14,119.38 101.6,118.43 | 91.12,118.75 101.28,118.75 101.6,118.43 | 91.76,101.6 91.76,95.88 | 91.76,101.6 82.23,101.6 | SW4.B SW4.A | SW2.B 74.3,142.24 | 49.53,142.24 48.58,141.29 48.58,110.81 | K1.1 173.99,111.76 172.72,113.03 C18.2 171.45,112.71 v155.57,112.71 152.4,112.71 150.5,110.81 | v34.61,85.09 34.61,86.68 | v34.61,85.09 34.61,83.5 | v29.53,111.44 27.62,111.44 | v29.53,111.44 29.53,113.35 | v29.53,111.44 29.53,109.86 | 40.96,145.73 v42.86,145.73 45.09,145.73 | v182.56,138.11 180.66,138.11 | v182.56,138.11 184.47,138.11 | v182.56,138.11 182.56,139.7 | v182.56,138.11 182.56,136.84 | v182.56,138.11 182.56,127 180.02,124.46 180.02,113.35 v181.93,113.35 | v150.5,80.01 150.5,81.6 | v150.5,80.01 150.5,78.42 | v150.5,80.01 148.91,80.01 | v150.5,80.01 152.08,80.01 | v48.58,102.24 48.58,104.14 | v48.58,102.24 48.58,100.65 | v104.46,102.24 C11.1 | v181.93,113.35 183.83,113.35 | v181.93,113.35 181.93,115.25 | 181.93,111.76 v181.93,113.35 | v149.22,102.24 150.18,101.28 | v149.22,102.24 148.27,103.19 | v104.46,102.24 106.05,102.24 106.05,96.52 108.59,93.98 108.59,85.41 108.27,85.09 108.27,83.5 JUM15.1
  Bottom 0.406: 96.2,101.6 101.92,101.6 102.55,102.24 v104.46,102.24 | v139.06,86.36 139.06,87.63 | v139.06,86.36 139.06,84.77 | v139.06,86.36 140.34,86.36 | v88.58,116.21 90.17,116.21 | v88.58,116.21 88.58,114.3 | 91.12,118.75 87.63,118.75 | 91.12,118.75 88.91,118.75 arc90 BAT1.- v88.58,116.21
  Bottom 0.61: 49.53,142.24 SW1.B 57.15,142.24 SW1.A SW2.B 73.66,142.24 74.3,142.24 SW2.A 78.42,142.24 | SW4.A 133.35,142.24 SW4.B SW3.A 116.84,142.24 SW3.B 109.54,142.24 | IO11.4 144.46,78.42 | 144.46,78.42 C17.2 | 144.46,78.42 C16.2
  other vias: 108.27,81.92 179.39,111.76
  pour Bottom (isolate 0.61): 0,75.25 186.06,75.25 186.06,147.64 0,147.64
  pour Top (isolate 0.61): 0,75.25 0,147.64 135.57,147.64 135.57,114.94 178.75,114.94 178.75,140.34 186.06,140.34 186.06,75.25
GND1
  pour Top (isolate 0.61): 0,149.54 186.06,149.54 186.06,221.93 0,221.93
IR
  Top 0.61: JUM12.1 105.73,78.42 104.78,79.38 100.97,79.38 R0.3.2
IR.
  Top 0.406: IO12.25 96.84,82.08 R0.3.1
IR_1
  Bottom 0.406: JUM12A.1 103.82,5.72 102.87,5.72 101.28,6.98 100.33,8.57 99.06,9.84 99.06,13.33 100.33,14.61 100.33,20.32 96.52,24.13 IO10.3
MISO  (via drill 0.6 pad 1.78)
  Top 0.406: IO12.16 87.8,91.12 81.6,91.12 77.79,87.31 77.79,80.96 76.84,80.01 48.9,80.01 46.36,82.55 46.36,86.36 45.09,87.63 ISP1.1 44.13,88.9 40.01,93.03 38.1,93.03 35.24,95.88 35.24,112.08 47.94,124.78 47.94,142.24 48.58,142.87 v48.58,145.73
  Bottom 0.406: v48.58,145.73 49.21,146.37 67.63,146.37 SW2.2 | R50.2 44.13,88.9 ISP1.1
MOSI
  Top 0.305: 87.63,89.85 88.9,89.85
  Top 0.406: IO12.15 89.53,90.52 89.53,90.17 89.22,89.85 88.9,89.85 | 87.63,89.85 82.87,89.85 80.65,87.63 80.65,80.01 79.69,79.06 46.67,79.06 41.59,84.14 ISP1.4
N$1
  Bottom 0.61: D2.A D1.K
N$2
  Bottom 0.61: D3.A D2.K
N$3
  Bottom 0.61: D4.A D3.K
N$4
  Bottom 0.61: D5.A D4.K
N$5
  Bottom 0.61: D7.A D6.K
N$6
  Bottom 0.406: D8.A D7.K
N$7
  Bottom 0.61: D9.A D8.K
N$8
  Bottom 0.61: D10.A D9.K
N$9
  Bottom 0.61: D12.A D11.K
N$10
  Bottom 0.61: D13.A D12.K
N$11
  Bottom 0.61: D14.A D13.K
N$12
  Bottom 0.61: D15.A D14.K
N$13
  Bottom 0.61: D17.A D16.K
N$14
  Bottom 0.61: D18.A D17.K
N$15
  Bottom 0.61: D19.A D18.K
N$16
  Bottom 0.61: D20.A D19.K
N$17
  Bottom 0.61: D22.A D21.K
N$18
  Bottom 0.61: D23.A D22.K
N$19
  Bottom 0.61: D24.A D23.K
N$20
  Bottom 0.61: D25.A D24.K
N$21
  Bottom 0.61: D27.A D26.K
N$22
  Bottom 0.61: D28.A D27.K
N$23
  Bottom 0.61: D29.A D28.K
N$24
  Bottom 0.61: D30.A D29.K
N$25
  Bottom 0.61: D32.A D31.K
N$26
  Bottom 0.61: D33.A D32.K
N$27
  Bottom 0.61: D34.A D33.K
N$28
  Bottom 0.61: D35.A D34.K
N$29
  Bottom 0.61: D36.K D37.A
N$30
  Bottom 0.61: D37.K D38.A
N$31
  Bottom 0.61: D38.K D39.A
N$32
  Bottom 0.61: D39.K D40.A
N$33
  Bottom 0.61: D42.A D41.K
N$34
  Bottom 0.61: D43.A D42.K
N$35
  Bottom 0.61: D44.A D43.K
N$36
  Bottom 0.61: D44.K D45.A
N$37
  Bottom 0.61: D47.A D46.K
N$38
  Bottom 0.61: D48.A D47.K
N$39
  Bottom 0.61: D49.A D48.K
N$40
  Bottom 0.61: D50.A D49.K
N$41
  Bottom 0.61: D52.A D51.K
N$42
  Bottom 0.61: D53.A D52.K
N$43
  Bottom 0.61: D54.A D53.K
N$44
  Bottom 0.61: D55.A D54.K
N$45
  Bottom 0.61: D57.A D56.K
N$46
  Bottom 0.61: D58.A D57.K
N$47
  Bottom 0.61: D59.A D58.K
N$48
  Bottom 0.61: D59.K D60.A
N$49
  Bottom 0.61: D61.K D62.A
N$50
  Bottom 0.61: D62.K D63.A
N$51
  Bottom 0.61: D63.K D64.A
N$52
  Bottom 0.61: D64.K D65.A
N$53
  Bottom 0.61: D67.A D66.K
N$54
  Bottom 0.61: D68.A D67.K
N$55
  Bottom 0.61: D69.A D68.K
N$56
  Bottom 0.61: D69.K D70.A
N$57
  Bottom 0.406: R1.1 37.78,66.36 37.47,66.04 D5.K
N$58
  Bottom 0.406: R2.1 39.05,31.11 36.51,33.65 D10.K
N$59
  Bottom 0.406: R3.2 39.05,7.94 36.51,5.4 D15.K
N$60
  Bottom 0.406: R4.2 33.66,35.88 6.03,35.88 D20.K
N$61
  Bottom 0.406: R7.2 33.97,39.05 32.7,37.78 D35.K
N$62
  Bottom 0.406: R5.2 33.34,68.58 33.02,68.26 7.3,68.26 5.08,66.04 D25.K
N$63
  Bottom 0.406: R6.2 33.34,70.8 32.7,70.17 D30.K
N$64
  Bottom 0.406: R8.2 80.96,66.36 80.65,66.04 D40.K
N$65
  Bottom 0.406: R9.2 82.23,31.11 79.69,33.65 D45.K
N$66
  Bottom 0.406: R10.2 82.23,7.94 79.69,5.4 D50.K
N$67
  Bottom 0.406: R11.2 76.84,35.88 49.21,35.88 D55.K
N$68
  Bottom 0.406: R12.2 76.52,68.58 76.2,68.26 49.21,68.26 D60.K
N$69
  Bottom 0.406: R13.2 76.52,70.8 75.88,70.17 D65.K
N$70
  Bottom 0.406: R14.2 77.15,39.05 75.88,37.78 D70.K
N$71
  Bottom 0.406: R36.2 43.18,6.98 42.86,6.67 D141.K
N$72
  Bottom 0.406: R37.2 86.36,6.98 86.04,6.67 D142.K
N$73
  Bottom 0.61: D71.K D72.A
N$74
  Bottom 0.61: D72.K D73.A
N$75
  Bottom 0.61: D73.K D74.A
N$76
  Bottom 0.61: D74.K D75.A
N$77
  Bottom 0.406: D76.K D77.A
N$78
  Bottom 0.406: D77.K D78.A
N$79
  Bottom 0.406: D78.K D79.A
N$80
  Bottom 0.406: D79.K D80.A
N$81
  Bottom 0.61: D82.A D81.K
N$82
  Bottom 0.61: D83.A D82.K
N$83
  Bottom 0.61: D84.A D83.K
N$84
  Bottom 0.61: D85.A D84.K
N$85
  Bottom 0.61: D86.K D87.A
N$86
  Bottom 0.61: D87.K D88.A
N$87
  Bottom 0.61: D88.K D89.A
N$88
  Bottom 0.61: D89.K D90.A
N$89
  Bottom 0.406: D91.K D92.A
N$90
  Bottom 0.406: D92.K D93.A
N$91
  Bottom 0.406: D93.K D94.A
N$92
  Bottom 0.406: D94.K D95.A
N$93
  Bottom 0.61: D97.A D96.K
N$94
  Bottom 0.61: D98.A D97.K
N$95
  Bottom 0.61: D99.A D98.K
N$96
  Bottom 0.61: D100.A D99.K
N$97
  Bottom 0.61: D102.A D101.K
N$98
  Bottom 0.61: D103.A D102.K
N$99
  Bottom 0.61: D104.A D103.K
N$100
  Bottom 0.61: D105.A D104.K
N$101
  Bottom 0.61: D106.K D107.A
N$102
  Bottom 0.61: D107.K D108.A
N$103
  Bottom 0.61: D108.K D109.A
N$104
  Bottom 0.61: D109.K D110.A
N$105
  Bottom 0.61: D111.K D112.A
N$106
  Bottom 0.61: D112.K D113.A
N$107
  Bottom 0.61: D113.K D114.A
N$108
  Bottom 0.61: D114.K D115.A
N$109
  Bottom 0.61: D117.A D116.K
N$110
  Bottom 0.61: D118.A D117.K
N$111
  Bottom 0.61: D119.A D118.K
N$112
  Bottom 0.61: D120.A D119.K
N$113
  Bottom 0.61: D121.K D122.A
N$114
  Bottom 0.61: D122.K D123.A
N$115
  Bottom 0.61: D123.K D124.A
N$116
  Bottom 0.61: D124.K D125.A
N$117
  Bottom 0.61: D126.K D127.A
N$118
  Bottom 0.61: D127.K D128.A
N$119
  Bottom 0.61: D128.K D129.A
N$120
  Bottom 0.61: D129.K D130.A
N$121
  Bottom 0.61: D132.A D131.K
N$122
  Bottom 0.61: D133.A D132.K
N$123
  Bottom 0.61: D134.A D133.K
N$124
  Bottom 0.61: D135.A D134.K
N$125
  Bottom 0.61: D137.A D136.K
N$126
  Bottom 0.61: D138.A D137.K
N$127
  Bottom 0.61: D139.A D138.K
N$128
  Bottom 0.61: D140.A D139.K
N$129
  Bottom 0.406: R15.1 109.54,68.58 109.86,68.26 136.84,68.26 D75.K
N$130
  Bottom 0.406: D80.K R16.1
N$131
  Bottom 0.406: R17.2 105.09,7.62 107.31,7.62 109.54,5.4 D85.K
N$132
  Bottom 0.406: R18.2 104.46,33.65 D90.K
N$133
  Bottom 0.406: R19.2 108.21,37.78 D105.K
N$134
  Bottom 0.406: D95.K R20.2
N$135
  Bottom 0.406: R21.2 109.22,70.8 109.86,70.17 D100.K
N$136
  Bottom 0.406: R22.2 152.72,68.58 153.03,68.26 180.02,68.26 D110.K
N$137
  Bottom 0.406: D115.K R23.2
N$138
  Bottom 0.406: R24.2 D120.K
N$139
  Bottom 0.406: R25.2 147.64,33.65 D125.K
N$140
  Bottom 0.406: D130.K R26.2
N$141
  Bottom 0.406: R27.2 152.4,70.8 153.03,70.17 D135.K
N$142
  Bottom 0.406: R28.2 151.45,37.78 D140.K
N$143
  Bottom 0.406: D143.K 141.29,3.49 109.22,3.49 106.05,6.67 103.5,6.67 102.23,7.94 R38.2
N$144
  Bottom 0.406: JUM5.2 41.91,128.27 41.27,127.64 41.27,124.78 42.86,123.19 IO1.16
N$145
  Bottom 0.61: D144.A 93.66,46.99 94.93,45.72 R39.1
N$146
  Bottom 0.61: D144.K 93.98,44.45 95.57,42.86 95.57,32.7 93.98,31.11 D145.A
N$147
  Bottom 0.406: IO5.7 IO1.1
N$148
  Bottom 0.406: IO5.6 IO1.2
N$149
  Bottom 0.406: IO5.5 IO1.3
N$150
  Bottom 0.406: IO5.4 IO1.4
N$151
  Bottom 0.406: IO5.3 IO1.5
N$152
  Bottom 0.406: IO5.2 IO1.6
N$153
  Bottom 0.406: IO5.1 IO1.7
N$154
  Bottom 0.406: R6.1 40.64,70.8 41.59,69.85 JUM1.1
N$155
  Bottom 0.406: R5.1 40.32,68.58 41.59,67.31 JUM1.2
N$156
  Bottom 0.406: R1.2 40.01,63.18 41.59,64.77 JUM1.3
N$157
  Bottom 0.406: R7.1 38.1,39.05 38.1,58.74 41.59,62.23 JUM1.4
N$158
  Bottom 0.406: R4.1 38.42,36.83 39.05,37.47 39.05,57.15 41.59,59.69 JUM1.5
N$159
  Bottom 0.406: R2.2 39.05,34.93 40.01,35.88 40.01,55.56 41.59,57.15 JUM1.6
N$160
  Bottom 0.406: R3.1 39.69,11.75 40.96,13.02 40.96,53.97 41.59,54.61 JUM1.7
N$161
  Bottom 0.406: R36.1 43.18,11.75 41.91,13.02 41.91,51.12 JUM1.8
N$162
  Bottom 0.406: R13.1 83.82,70.8 84.77,69.85 JUM2.1
N$163
  Bottom 0.406: R12.1 83.5,68.58 84.77,67.31 JUM2.2
N$164
  Bottom 0.406: R8.1 83.19,63.18 84.77,64.77 JUM2.3
N$165
  Bottom 0.406: JUM2.4 85.09,62.23 81.28,58.42 81.28,39.05 arc-90 R14.1
N$166
  Bottom 0.406: JUM2.5 85.09,59.69 82.23,56.83 82.23,37.47 81.6,36.83 R11.1
N$167
  Bottom 0.406: JUM2.6 85.09,57.15 83.19,55.24 83.19,35.88 82.23,34.93 R9.1
N$168
  Bottom 0.406: JUM2.7 85.09,54.61 84.14,53.66 84.14,13.02 82.87,11.75 R10.1
N$169
  Bottom 0.406: JUM2.8 85.09,51.12 85.09,13.02 86.36,11.75 R37.1
N$170
  Bottom 0.406: R21.1 101.92,70.8 100.97,69.85 JUM3.1
N$171
  Bottom 0.406: JUM3.2 100.97,66.04 R20.1
N$172
  Bottom 0.406: R15.2 104.14,68.58 103.5,67.94 103.5,64.77 102.87,64.13 100.33,64.13 JUM3.3
N$173
  Bottom 0.406: JUM3.4 100.97,62.23 104.78,58.42 104.78,39.69 R19.1
N$174
  Bottom 0.406: JUM3.5 100.97,59.69 103.82,56.83 103.82,36.83 R18.1
N$175
  Bottom 0.406: JUM3.6 100.97,57.15 102.87,55.24 102.87,35.88 103.19,35.56 105.41,35.56 105.73,35.88 135.89,35.88 136.84,36.83 136.84,37.47 138.11,38.73 R16.2
N$176
  Bottom 0.406: JUM3.7 100.97,54.61 101.92,53.66 101.92,33.65 104.46,31.11 R17.1
N$177
  Bottom 0.406: JUM3.8 100.97,50.8 100.97,33.34 103.19,31.11 103.19,13.97 102.23,13.02 R38.1
N$178
  Bottom 0.406: R27.1 145.1,70.8 144.14,69.85 JUM4.1
N$179
  Bottom 0.406: R26.1 144.14,66.04 JUM4.2
N$180
  Bottom 0.406: R22.1 147.32,68.58 146.69,67.94 146.69,64.77 146.05,64.13 143.51,64.13 JUM4.3
N$181
  Bottom 0.406: R28.1 147.95,39.69 147.95,58.42 144.14,62.23 JUM4.4
N$182
  Bottom 0.406: R25.1 147,36.83 147,56.83 144.14,59.69 JUM4.5
N$183
  Bottom 0.406: JUM4.6 144.14,57.15 146.05,55.24 146.05,35.88 146.37,35.56 148.59,35.56 148.91,35.88 179.07,35.88 180.02,36.83 180.02,37.47 181.29,38.73 R23.1
N$184
  Bottom 0.406: JUM4.7 144.14,54.61 145.1,53.66 145.1,10.48 148.91,6.67 R24.1
N$185
  Bottom 0.406: JUM5.3 41.59,130.81 40.32,129.54 40.32,124.46 41.59,123.19 IO1.15
N$186
  Bottom 0.406: IO1.14 40.32,123.19 39.37,124.14 39.37,131.13 41.59,133.35 JUM5.4
N$187
  Bottom 0.406: JUM5.5 41.59,135.89 38.42,132.72 38.42,123.83 39.05,123.19 IO1.13
N$188
  Bottom 0.406: JUM5.6 41.59,138.43 37.47,134.3 37.47,123.51 37.78,123.19 IO1.12
N$189
  Bottom 0.406: JUM5.7 41.59,140.97 36.51,135.89 IO1.11
N$190
  Bottom 0.406: JUM5.8 41.59,143.51 35.56,137.48 35.56,123.51 35.24,123.19 IO1.10
N$191  (via drill 0.6 pad 1.68)
  Top 0.406: R41.1 v46.36,115.57
  Bottom 0.406: v46.36,115.57 T1.1
N$192
  Bottom 0.406: JUM5.1 45.4,123.19 T1.3
N$193  (via drill 0.6 pad 1.42)
  Top 0.406: R41.2 40.32,115.57 36.2,111.44 36.2,103.51 37.15,102.55 v37.78,102.55
  Bottom 0.406: IO5.15 36.51,105.73 36.2,105.41 36.2,103.51 37.15,102.55 v37.78,102.55
N$194
  Bottom 0.406: IO6.7 IO2.1
N$195
  Bottom 0.406: IO6.6 IO2.2
N$196
  Bottom 0.406: IO6.5 IO2.3
N$197
  Bottom 0.406: IO6.4 IO2.4
N$198
  Bottom 0.406: IO6.3 IO2.5
N$199
  Bottom 0.406: IO6.2 IO2.6
N$200
  Bottom 0.406: IO6.1 IO2.7
N$201
  Bottom 0.406: JUM6.2 85.09,128.27 84.45,127.64 84.45,124.78 86.04,123.19 IO2.16
N$202
  Bottom 0.406: JUM6.3 84.77,130.81 83.5,129.54 83.5,124.46 84.77,123.19 IO2.15
N$203
  Bottom 0.406: JUM6.4 84.77,133.35 82.55,131.13 82.55,124.14 83.5,123.19 IO2.14
N$204
  Bottom 0.406: JUM6.5 84.77,135.89 81.6,132.72 81.6,123.83 82.23,123.19 IO2.13
N$205
  Bottom 0.406: JUM6.6 84.77,138.43 80.65,134.3 80.65,123.51 80.96,123.19 IO2.12
N$206
  Bottom 0.406: JUM6.7 84.77,140.97 79.69,135.89 IO2.11
N$207
  Bottom 0.406: JUM6.8 84.77,143.51 78.74,137.48 78.74,123.51 78.42,123.19 IO2.10
N$208  (via drill 0.6 pad 1.68)
  Top 0.406: R42.1 85.09,120.01 86.68,121.6 v89.22,121.6
  Bottom 0.406: T2.1 89.22,123.19 v89.22,121.6
N$209
  Bottom 0.406: JUM6.1 T2.3
N$210  (via drill 0.6 pad 1.42)
  Top 0.406: R42.2 85.09,104.14 83.5,102.55 v80.96,102.55
  Bottom 0.406: IO6.15 79.69,105.73 79.38,105.41 79.38,104.14 v80.96,102.55
N$211
  Bottom 0.406: C6.+ R29.2
  Bottom 0.61: IO10.2 91.44,21.59 C6.+
N$212
  Bottom 0.406: IO7.7 IO3.1
N$213
  Bottom 0.406: IO7.6 IO3.2
N$214
  Bottom 0.406: IO7.5 IO3.3
N$215
  Bottom 0.406: IO7.4 IO3.4
N$216
  Bottom 0.406: IO7.3 IO3.5
N$217
  Bottom 0.406: IO7.2 IO3.6
N$218
  Bottom 0.406: IO7.1 IO3.7
N$219
  Bottom 0.406: IO3.16 100.01,123.19 98.11,125.09 98.11,127.32 99.06,128.27 JUM7.2
N$220
  Bottom 0.406: IO3.15 98.74,123.19 97.16,124.78 97.16,129.54 98.42,130.81 JUM7.3
N$221
  Bottom 0.406: JUM7.4 98.42,133.35 96.2,131.13 96.2,124.46 97.47,123.19 IO3.14
N$222
  Bottom 0.406: IO3.13 96.2,123.19 95.25,124.14 95.25,132.72 98.42,135.89 JUM7.5
N$223
  Bottom 0.406: IO3.12 94.93,123.19 94.3,123.83 94.3,129.54 | 94.3,129.54 94.3,129.86 | JUM7.6 98.42,138.43 94.3,134.3 94.3,129.54
N$224
  Bottom 0.406: IO3.11 93.66,123.19 93.34,123.51 93.34,135.89 98.42,140.97 JUM7.7
N$225
  Bottom 0.406: JUM7.8 98.42,143.51 92.39,137.48 IO3.10
N$226  (via drill 0.6 pad 1.42)
  Top 0.406: v103.19,114.94 91.76,114.94 90.81,113.98 R43.1
  Bottom 0.406: v103.19,114.94 103.19,115.89 103.5,116.21 T3.1
N$227
  Bottom 0.406: JUM7.1 102.55,122.87 T3.3
N$228  (via drill 0.6 pad 1.42)
  Top 0.406: v90.81,107 R43.2
  Bottom 0.406: IO7.15 93.66,106.04 93.03,105.41 91.44,105.41 90.81,106.04 v90.81,107
N$229
  Bottom 0.406: IO8.7 IO4.1
N$230
  Bottom 0.406: IO8.6 IO4.2
N$231
  Bottom 0.406: IO8.5 IO4.3
N$232
  Bottom 0.406: IO8.4 IO4.4
N$233
  Bottom 0.406: IO8.3 IO4.5
N$234
  Bottom 0.406: IO8.2 IO4.6
N$235
  Bottom 0.406: IO8.1 IO4.7
N$236  (via drill 0.2 pad 1.68)
  Top 0.406: v147,124.14 v147,127.32
  Bottom 0.406: 145.42,122.24 IO4.16 145.42,122.55 v147,124.14 | JUM8.2 144.46,128.27 145.42,127.32 v147,127.32
N$237  (via drill 0.6 pad 1.68)
  Top 0.406: v144.78,124.14 v144.78,130.81 JUM8.3
  Bottom 0.406: IO4.15 144.14,123.51 v144.78,124.14
  Bottom 0.61: v144.78,130.81 JUM8.3
N$238
  Bottom 0.406: IO4.14 142.88,123.19 140.34,125.73 140.34,132.08 141.61,133.35 JUM8.4
N$239
  Bottom 0.406: JUM8.5 141.61,135.89 139.38,133.67 139.38,125.41 141.61,123.19 IO4.13
N$240
  Bottom 0.406: JUM8.6 141.61,138.43 138.43,135.26 138.43,125.09 140.34,123.19 IO4.12
N$241
  Bottom 0.406: JUM8.7 141.61,140.97 137.48,136.84 137.48,124.78 139.06,123.19 IO4.11
N$242
  Bottom 0.406: IO4.10 137.8,123.19 136.53,124.46 136.53,138.43 141.61,143.51 JUM8.8
N$243
  Bottom 0.406: R0.2.2 148.91,105.41 145.73,102.24 R44.1
N$244
  Bottom 0.406: JUM8.1 148.27,125.73 148.91,125.09 148.91,122.87 147.95,121.92 T4.3
N$245
  Bottom 0.406: IO8.15 139.06,105.73 138.75,105.41 138.75,102.87 139.38,102.24 R44.2
N$246
  Bottom 0.406: JUM14A.1 99.06,5.72 98.42,7.3 96.84,8.89 96.84,13.97 98.11,15.24 T8.1
N$248
  Bottom 0.61: JUM14.1 R47.1
N$249
  Bottom 0.406: R0.2.1 T4.1
N$250  (via drill 0.6 pad 1.78)
  Bottom 0.61: JUM13A.1 88.27,7.3 89.21,8.25 P1.3 89.21,17.15 87.31,19.37 87.31,29.21 87.95,29.84 89.85,29.84 90.49,30.48 R30.1 90.49,49.85 | 90.49,49.85 90.49,51.12 v91.44,52.07 | 90.49,49.85 v88.9,49.85
N$251
  Bottom 0.61: IO9.14 87.63,89.53 86.02,91.14 BAT1.+
N$252
  Bottom 0.61: T5.3 REP1.-
N$253  (via drill 0.6 pad 1.68)
  Top 0.406: v48.58,93.03 48.58,82.23 49.53,81.28 76.52,81.28 76.84,81.6 76.84,92.08 77.79,93.03 R45.2
  Bottom 0.61: v48.58,93.03 T5.1
N$254  (via drill 0.6 pad 1.68)
  Top 0.406: v145.1,146.05 145.1,144.46 | 149.22,138.75 149.22,137.48 148.59,136.84 148.59,132.4
  Top 0.61: T6.2 T6.4 149.15,145.1 148.27,146.05 v145.1,146.05
  Top 0.813: JUM9.1 v145.1,146.05
  Bottom 0.813: JUM9.1 v145.1,146.05
  pour Top (isolate 0.61): 135.57,147.64 178.75,147.64 178.75,118.75 135.57,118.75
N$255
  Top 0.406: R34.2 R35.1 147,138.73 T6.1
N$256
  Top 0.406: 83.5,84.45 83.5,86.04 85.09,87.63 86.04,87.63 86.64,87.03 C13.1 87.38,87.03 IO12.18
  Top 1.27: L1.2 83.5,84.45 82.55,84.45
  Bottom 1.27: L1.2 82.87,84.45
N$257  (via drill 0.6 pad 1.93)
  Top 0.406: IO12.8 95.88,96.67 v95.88,98.74 | v95.88,98.74 Q1.1 | v95.88,98.74 97.16,98.74 100.65,102.24 C11.2
N$258  (via drill 0.6 pad 1.93)
  Top 0.406: IO12.7 99.09,98.74 v100.97,98.74 102.23,98.74 | 102.23,98.74 Q1.2 | C10.2 102.55,98.74 102.23,98.74
N$259
  Top 0.61: R0.4.2 86.36,76.83 87,77.47 JUM13.1
N$261
  Top 0.406: R46.2 96.52,125.09 104.78,116.84 104.78,113.98 105.73,113.03 142.88,113.03 146.37,116.52 T7.1
N$262
  Top 0.406: IO12.20 88.37,85.76 C14.1
N$263
  Top 0.406: IO12.2 98.08,92.08 NC2.1
N$265
  Top 0.406: IO12.12 88.83,94.61 85.09,94.61 80.65,99.06 NC1.1
N$266
  Top 0.406: IO12.23 91.41,85.37 88.27,82.23 NC3.1
N$268
  Top 0.406: J1.2 78.11,123.83 87,123.83 88.27,125.09 R46.1
N$269  (via drill 0.6 pad 1.78)
  Top 0.406: v106.36,142.24 106.36,117.47 J2.2
  Bottom 0.406: SW3.2 110.17,144.78 107.63,142.24 v106.36,142.24
N$270  (via drill 0.6 pad 1.78)
  Top 0.406: J3.2 v108.59,145.73
  Bottom 0.406: v108.59,145.73 109.22,146.37 127.32,146.37 SW4.2
N$271
  Top 0.406: R34.1 150.18,121.29 148.59,119.7 T7.3
N$272
  Bottom 0.406: T8.3 95.88,18.41 94.62,19.69 94.62,22.54 93.34,23.81 93.34,27.3 93.03,27.62 D145.K
PIEZO
  Top 0.406: IO12.14 88.47,92.71 83.5,92.71 83.19,93.03 R45.1 81.6,92.71
PWM
  Top 0.406: IO12.13 88.65,93.66 84.14,93.66 80.96,96.84 79.06,96.84 77.15,98.74 J1.1
RESET
  Top 0.305: 93.03,84.45 93.03,85.72
  Top 0.406: ISP1.5 38.1,87.63 37.15,86.68 37.15,83.5 43.5,77.15 81.28,77.15 82.55,78.42 | 93.03,84.45 93.03,83.82 91.76,82.55 91.12,82.55 87.95,79.38 87,79.38 86.04,78.42 82.55,78.42 | 93.03,85.72 93.03,86.68 94.3,87.95 95.5,87.95 IO12.29 | 82.55,78.42 R40.1
RFOTO.
  Top 0.406: IO12.24 87.78,80.64 86.68,80.64 86.04,80.01 R0.4.1
RTC-SCL  (via drill 0.6 pad 1.68)
  Top 0.406: IO12.31 98.4,87.31 v100.01,87.31
  Bottom 0.406: IO9.16 94.62,87 | 94.62,87 R31.1 | 94.62,87 98.74,87 99.06,87.31 v100.01,87.31
RTC-SDA  (via drill 0.6 pad 1.68)
  Top 0.406: v100.01,89.53 99.28,88.8 IO12.32
  Bottom 0.406: IO9.15 91.76,88.27 93.34,89.85 97.16,89.85 | 97.16,89.85 R32.1 | 97.16,89.85 98.74,89.85 99.06,89.53 v100.01,89.53
SCK  (via drill 0.6 pad 1.78)
  Top 0.305: 40.32,84.14 40.32,86.04
  Top 0.406: IO12.17 87.91,88.9 83.5,88.9 81.28,86.68 81.28,79.06 80.33,78.1 45.09,78.1 40.32,82.87 40.32,84.14 | 40.32,86.04 40.32,86.36 ISP1.3 41.59,89.22 39.05,91.76 37.47,91.76 34.29,94.93 34.29,112.71 46.67,125.09 v46.67,143.51
  Bottom 0.406: SW1.2 50.48,144.78 49.21,143.51 v46.67,143.51 | R49.2 41.59,88.27 ISP1.3
STROBE  (via drill 0.6 pad 1.42)
  Top 0.406: v83.5,104.77 83.5,108.58 80.65,111.44 46.67,111.44 44.13,108.9 44.13,103.82 43.5,103.19 41.91,103.19 v40.32,104.77 | v142.88,104.77 142.88,108.27 140.97,110.17 103.19,110.17 100.65,107.63 100.65,104.14 99.7,103.19 v97.47,103.19 v94.93,103.19 93.03,103.19 90.81,100.97 90.81,96.03 IO12.9
  Bottom 0.406: v40.32,104.77 IO5.12 | IO6.12 v83.5,104.77 85.09,103.19 v94.93,103.19 | v97.47,103.19 IO7.12 | v142.88,104.77 IO8.12
SW3
  Top 0.406: IO12.28 97.54,84.77 100.97,84.77 101.92,85.72 104.46,85.72 107.31,88.58 107.31,103.51 106.36,104.46 J2.1
  Bottom 0.406: R52.1 107.63,103.19 106.36,104.46 J2.1
SW4
  Top 0.406: IO12.27 97.36,83.82 101.28,83.82 102.23,84.77 105.09,84.77 108.59,88.27 J3.1
  Bottom 0.406: J3.1 108.59,104.14 109.22,103.51 109.22,98.74 108.27,97.79 R51.1
TECKY  (via drill 0.6 pad 1.78)
  Top 0.406: IO12.30 98.85,85.72 100.65,85.72 102.23,87.31 v103.82,87.31
  Bottom 0.406: R47.2 100.97,83.5 103.82,86.36 v103.82,87.31
VCC  (via drill 0.6 pad 1.78, 0.6 pad 1.93, 0.8 pad 2.18)
  Top 0.406: R35.2 151.76,135.89 151.76,135.57
  Top 0.813: 151.45,138.82 T6.3
  Top 1.016: 151.45,98.11 C7.+ | 151.45,88.9 151.45,98.11 | 151.45,88.9 C8.+ | v150.5,83.82 151.45,84.77 151.45,88.9 | 151.45,98.11 151.76,110.17 | 151.76,110.17 151.76,135.57 151.76,137.48 151.45,137.79 151.45,138.82 | 151.76,110.17 v155.57,110.17 | K1.3 v181.93,109.86
  Bottom 0.406: 171.45,109.22 C18.1
  Bottom 0.813: IO11.1 146.69,85.41 | v150.5,83.82 147.24,83.82 IO11.1 | C16.1 147,83.66 IO11.1
  Bottom 1.016: K1.3 K1.2 | K1.3 176.21,109.22 171.45,109.22 155.57,109.22 | 155.57,109.22 v155.57,110.17 | K1.3 v181.93,109.86 | 155.57,109.22 152.4,109.22 152.08,108.9 152.08,85.41 v150.5,83.82
  Bottom 1.27: 146.69,85.41 146.69,87.95
(copper drawn outside any net)
  shapes: Bottom area x3, Bottom circle x1030, Top circle x514

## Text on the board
Top: www.paja-trb.cz | PaJa | Hodiny | vzdusne | 2013-2014 | DS18B20 | hodiny | PaJa | +12V LED | +12V
Bottom: Hodiny 2013 vzdusne | 1 | 2 | 3 | 4 | PaJa | +5V | www.paja-trb.cz | +5V | AVR-ISP | PaJa | +12V
tPlace: R-f
tValues: A906013
Propoje: DS18B20
stitek: Hodiny vzdusné | DS18B20 | PaJa-trb 2013-2014 | www.paja-trb.cz | Gnd 1wire +5V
